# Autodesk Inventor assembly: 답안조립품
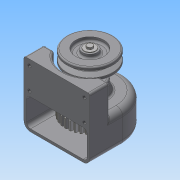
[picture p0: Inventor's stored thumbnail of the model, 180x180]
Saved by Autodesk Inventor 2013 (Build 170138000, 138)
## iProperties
Created: 2015-02
Part Number: 답안조립품
Document SubType Name: Assembly
Designer: Administrator
Author: Administrator
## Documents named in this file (14)
- C:\Documents and Settings\Administrator\바탕 화면\450214V1027\답안조립품.iam
- C:\Documents and Settings\Administrator\바탕 화면\450214V1027\1-본체.ipt
- C:\Documents and Settings\Administrator\바탕 화면\450214V1027\베어링 6001.ipt
- C:\Documents and Settings\Administrator\바탕 화면\450214V1027\축.ipt
- C:\Documents and Settings\Administrator\바탕 화면\450214V1027\키5x5.ipt
- C:\Documents and Settings\Administrator\바탕 화면\450214V1027\키4x4.ipt
- C:\Documents and Settings\Administrator\바탕 화면\450214V1027\스퍼기어.ipt
- C:\Documents and Settings\Administrator\바탕 화면\450214V1027\축커버.ipt
- C:\Documents and Settings\Administrator\바탕 화면\450214V1027\오일실.ipt
- C:\Documents and Settings\Administrator\바탕 화면\450214V1027\M3x0.5.ipt
- C:\Documents and Settings\Administrator\바탕 화면\450214V1027\4-벨트풀리.ipt
- C:\Documents and Settings\Administrator\바탕 화면\450214V1027\와샤.ipt
- C:\Documents and Settings\Administrator\바탕 화면\450214V1027\M5x0.8.ipt
- M5x0.8.ipt
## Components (7 placed, 4 different names)
1. 1-본체:1
2. 4-벨트풀리:1 — 각도:4
3. M5x0.8:1
4. M3x0.5:1
5. M3x0.5:2
6. M3x0.5:3
7. M3x0.5:4
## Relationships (1: Angle 1)
- 각도:4 [Angle]: 4-벨트풀리:1
